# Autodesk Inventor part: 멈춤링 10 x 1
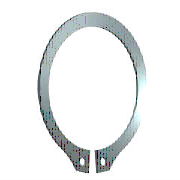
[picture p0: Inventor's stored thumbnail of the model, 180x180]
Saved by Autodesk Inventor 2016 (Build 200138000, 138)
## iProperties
IsCustomPart: 0
Created: 2015-11
Part Number: 멈춤링 10 x 1
Material: 스테인리스강
Description: 리테이닝 링(C형)
Document SubType Name: Modeling
Standard: KS B 1336
Designer: mdu
Standards Organization: KS
Language: ko-KR
Size Designation: 10 x 1
Categories: <MemberInstance><Categories><Category DisplayName="샤프트 부품" InternalName="7f7aeb1f-a693-4053-b835-cee3144e0d98" Mnemonic="SHFT"><Category DisplayName="써클립" Inter
Density: 8.08 g/cm^3
Mass: 0.434929 g
Surface Area: 1.9243 cm^2
Volume: 0.0538279 cm^3
Appearance: 반광택
Author: mdu
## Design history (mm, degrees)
sketch "스케치1"
  geometry: L1 (-6, 0)-(6, 0) reference; L2 (0, 20.189)-(0, -80.536) reference; L3 (-48.09, 0)-(48.09, 0) reference; L4 (-0.3, -9.791)-(-0.3, -12.791); L5 (-0.3, -6.54)-(-0.3, -13.29); L6 (-2.795, 1.6)-(3.672, 1.6); L7 (0.3, -6.54)-(0.3, -13.29); L8 (0.3, -9.791)-(0.3, -12.791); C1 r 0.6 at (-1.2, -11.486); C2 r 0.6 at (1.2, -11.486); A1 r 4.8 centre (0, -5) between (0.3, -9.791) and (-0.3, -9.791); A2 r 6.2 centre (0, -4.6) between (2.988, -10.033) and (-2.988, -10.033); A3 r 7.796 centre (0, -5) between (-1.418, -12.666) and (-0.3, -12.791); A4 r 1.2 centre (-1.2, -11.486) between (-2.383, -11.285) and (-1.418, -12.666); A5 r 1.2 centre (-3.566, -11.084) between (-2.383, -11.285) and (-2.988, -10.033); A6 r 1.2 centre (3.566, -11.084) between (2.988, -10.033) and (2.383, -11.285); A7 r 1.2 centre (1.2, -11.486) between (1.418, -12.666) and (2.383, -11.285); A8 r 7.796 centre (0, -5) between (0.3, -12.791) and (1.418, -12.666)
  constraints: 16 point on circle, 12 end point, 10 centre point, 9 symmetric about line, 5 point on line, 4 tangent, 3 coincident, 2 horizontal, 1 perpendicular, 1 vertical, 5 other
  dimensions: "d0" = 9.6 diameter of A1 (= ND); "d1" = 3 distance of L4.end L4.start (= SRB2); "d6" = 0.3 distance between parallel lines of L2 L5 (= 0.25 x SD5); "d7" = 1.6 distance between parallel lines of L6 L3 (= SRB1); "d8" = 0.4 distance of A1.centre A2.centre (= 0.25 x SRB1); "d9" = 1.2 radius of A4 (= SD5); "d10" = 1.2 radius of A5 (= SD5); "d11" = 0.9 distance from line of L4 A4.centre (= 0.75 x SD5); "d12" = 1.2 diameter of C1 (= SD5); "d13" = 1.2 diameter of C2 (= SD5); "d14" = 5 distance from line of A1.centre L1 (= 0.5 x WD)
extrude "본체" new body sketch "스케치1" distance "d2" = 1 (= SD); taper "d3" = 0 deg
workaxis "Work Axis1"
workplane "Work Plane1"
body "Solid1"
other parameters: "SD" = 1 [user parameter; used in 1 equation term], "SRB1" = 1.6 [user parameter; used in 2 equation terms], "ND" = 9.6 [user parameter; used in 1 equation term], "SRB2" = 3 [user parameter; used in 1 equation term], "SD5" = 1.2 [user parameter; used in 6 equation terms], "d15" = 0, "d16" = 0, "d17" = 0, "d41" = 0, "d42" = 0, "SD3" = 9.3 [user parameter], "WDMAX" = 11 [user parameter]
